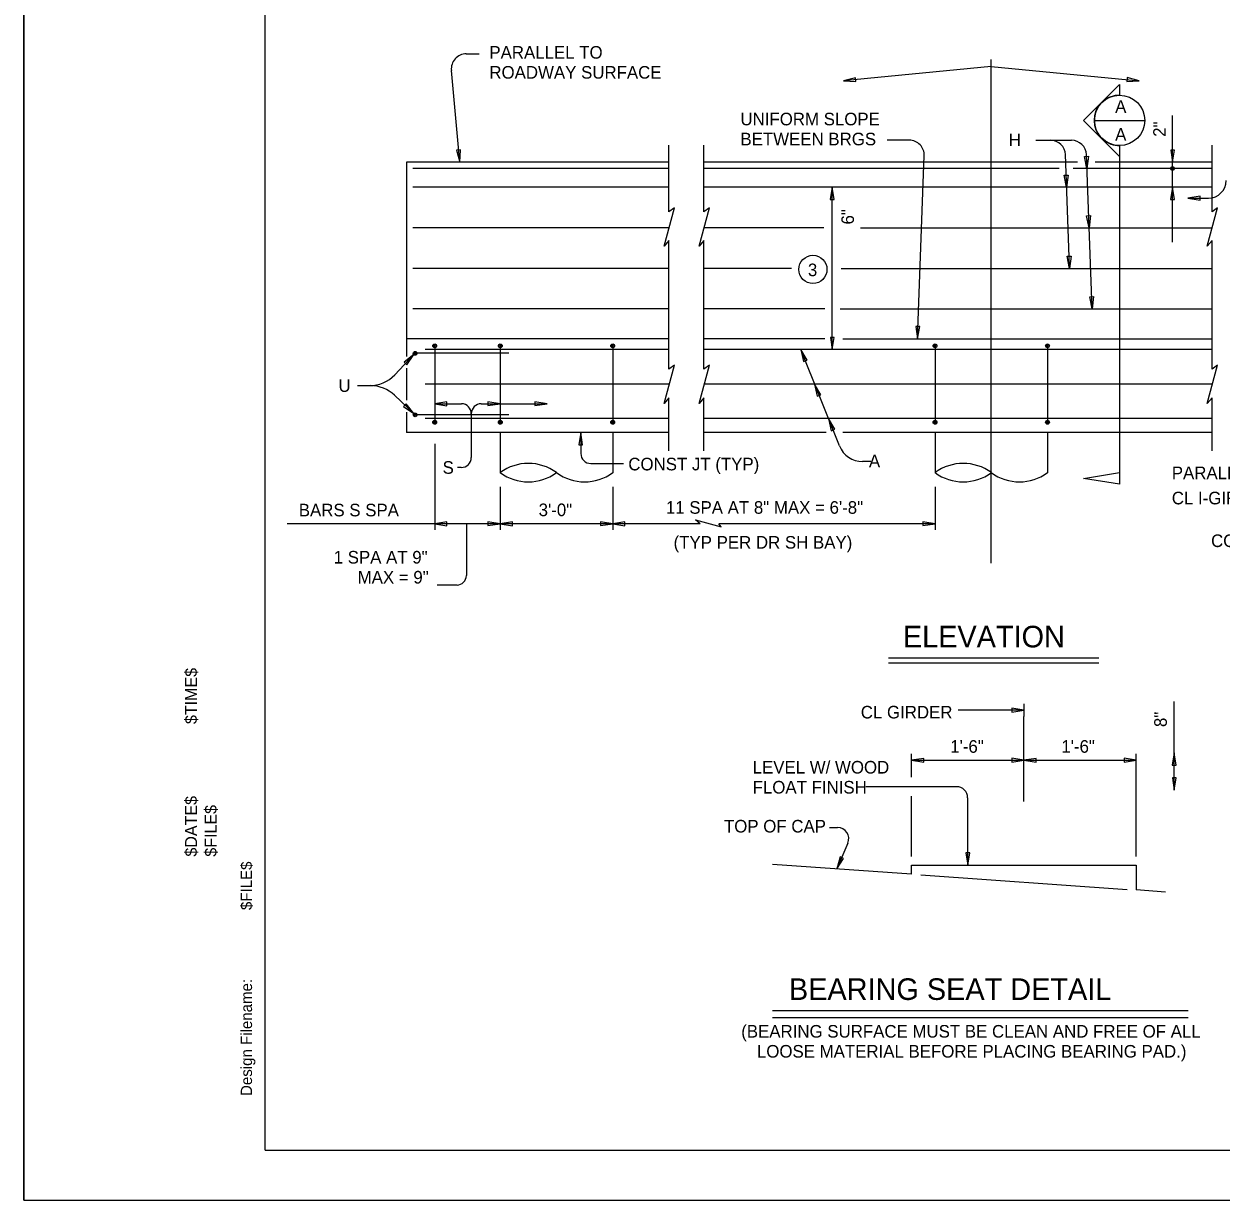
# Model space of a CAD drawing. Extents: x 970 to 1074, y 989 to 1045.
# Drawn here: x 1000 to 1011.98, y 997.81 to 1009.58 of the extents above; entities that cross this region are included whole.
import ezdxf

# ---------------------------------------------------------------- set-up
doc = ezdxf.new("R2010")
doc.units = 0
for name, color, linetype in [('BORD_lines_major', 7, 'Continuous'), ('BORD_text_filename_date', 7, 'Continuous'), ('D_BATCH_PLOT', 7, 'Continuous'), ('D_SHEET', 7, 'Continuous'), ('D_SHEET_TXT_SUB_CODE', 7, 'Continuous'), ('Default', 7, 'Continuous'), ('Working Level 1', 7, 'Continuous')]:
    doc.layers.add(name, color=color, linetype=linetype)

msp = doc.modelspace()

# ---------------------------------------------------------------- linework, layer by layer
at = {"layer": 'BORD_lines_major'}
for q in [(1002.413, 1019.195), (1033.5, 998.313)]:
    msp.add_line((1002.413, 998.313), q, dxfattribs=at)
at = {"layer": 'D_BATCH_PLOT'}
msp.add_lwpolyline([(1000, 997.813), (1034, 997.813), (1034, 1019.813), (1000, 1019.813)], close=True, dxfattribs=at)
at = {"layer": 'D_SHEET'}
for q in [(1000, 1019.813), (1034, 997.813)]:
    msp.add_line((1000, 997.813), q, dxfattribs=at)
at = {"layer": 'Default'}
msp.add_line((1010.71, 1008.614), (1011.214, 1008.614), dxfattribs=at)
for points in [[(1010.962, 1008.866), (1010.94, 1008.865), (1010.919, 1008.862), (1010.897, 1008.857), (1010.876, 1008.851), (1010.856, 1008.842), (1010.836, 1008.832), (1010.818, 1008.82), (1010.8, 1008.807), (1010.784, 1008.792), (1010.769, 1008.776), (1010.756, 1008.759), (1010.744, 1008.74), (1010.734, 1008.721), (1010.726, 1008.7), (1010.719, 1008.679), (1010.714, 1008.658), (1010.711, 1008.636), (1010.71, 1008.614), (1010.711, 1008.592), (1010.714, 1008.57), (1010.719, 1008.549), (1010.726, 1008.528), (1010.734, 1008.508), (1010.744, 1008.488), (1010.756, 1008.469), (1010.769, 1008.452), (1010.784, 1008.436), (1010.8, 1008.421), (1010.818, 1008.408), (1010.836, 1008.396), (1010.856, 1008.386), (1010.876, 1008.377), (1010.897, 1008.371), (1010.919, 1008.366), (1010.94, 1008.363), (1010.962, 1008.362), (1010.962, 1008.254), (1010.602, 1008.614), (1010.962, 1008.974)], [(1010.962, 1004.975), (1010.602, 1005.033), (1010.962, 1005.091)]]:
    msp.add_lwpolyline(points, close=True, dxfattribs=at)
msp.add_lwpolyline([(1010.962, 1008.362), (1010.962, 1004.975)], dxfattribs=at)
msp.add_circle((1010.962, 1008.614), 0.252, dxfattribs=at)
at = {"layer": 'Working Level 1'}
for p, q in [((1004.426, 1009.28), (1004.555, 1009.28)), ((1009.679, 1009.152), (1008.199, 1009.011)), ((1009.679, 1004.183), (1009.679, 1009.225)), ((1009.679, 1009.152), (1011.158, 1009.011)), ((1004.36, 1008.195), (1004.277, 1009.114)), ((1011.493, 1007.397), (1011.493, 1008.665)), ((1008.858, 1008.416), (1008.636, 1008.416)), ((1010.125, 1008.416), (1010.481, 1008.416)), ((1006.453, 1007.699), (1006.453, 1008.368)), ((1006.804, 1007.699), (1006.804, 1008.368)), ((1011.888, 1007.699), (1011.888, 1008.368)), ((1006.453, 1008.195), (1003.828, 1008.195)), ((1003.828, 1008.195), (1003.828, 1006.43)), ((1010.541, 1008.195), (1006.804, 1008.195)), ((1008.939, 1006.43), (1009.008, 1008.261)), ((1010.463, 1007.155), (1010.421, 1008.272)), ((1010.688, 1006.728), (1010.63, 1008.272)), ((1011.888, 1008.195), (1010.719, 1008.195)), ((1006.453, 1008.133), (1003.891, 1008.133)), ((1010.358, 1008.133), (1006.804, 1008.133)), ((1011.888, 1008.133), (1010.497, 1008.133)), ((1006.453, 1007.945), (1003.891, 1007.945)), ((1011.888, 1007.945), (1006.804, 1007.945)), ((1008.088, 1006.322), (1008.088, 1007.945)), ((1011.645, 1007.837), (1011.853, 1007.837)), ((1006.405, 1007.355), (1006.509, 1007.739)), ((1006.509, 1007.739), (1006.453, 1007.699)), ((1006.755, 1007.355), (1006.859, 1007.739)), ((1006.859, 1007.739), (1006.804, 1007.699)), ((1011.839, 1007.355), (1011.943, 1007.739)), ((1011.943, 1007.739), (1011.888, 1007.699)), ((1006.455, 1007.539), (1003.891, 1007.539)), ((1008.003, 1007.539), (1006.805, 1007.539)), ((1008.37, 1007.539), (1011.889, 1007.539)), ((1006.453, 1007.413), (1006.405, 1007.355)), ((1006.453, 1006.126), (1006.453, 1007.413)), ((1006.804, 1007.413), (1006.755, 1007.355)), ((1006.804, 1006.126), (1006.804, 1007.413)), ((1011.888, 1007.413), (1011.839, 1007.355)), ((1011.888, 1006.126), (1011.888, 1007.413)), ((1006.453, 1007.134), (1003.891, 1007.134)), ((1007.68, 1007.134), (1006.804, 1007.134)), ((1008.176, 1007.134), (1011.888, 1007.134)), ((1006.453, 1006.728), (1003.891, 1006.728)), ((1008.015, 1006.728), (1006.804, 1006.728)), ((1008.167, 1006.728), (1011.888, 1006.728)), ((1006.453, 1006.43), (1003.828, 1006.43)), ((1003.828, 1006.43), (1003.828, 1006.251)), ((1008.015, 1006.43), (1006.804, 1006.43)), ((1008.194, 1006.43), (1009.679, 1006.43)), ((1009.669, 1006.43), (1011.888, 1006.43)), ((1003.901, 1006.271), (1003.711, 1006.07)), ((1004.852, 1006.284), (1003.914, 1006.284)), ((1006.453, 1006.322), (1004.016, 1006.322)), ((1004.11, 1006.359), (1004.11, 1005.594)), ((1004.766, 1006.359), (1004.766, 1005.594)), ((1005.891, 1006.359), (1005.891, 1005.594)), ((1011.888, 1006.322), (1006.804, 1006.322)), ((1008.159, 1005.358), (1007.772, 1006.322)), ((1009.116, 1006.359), (1009.116, 1005.594)), ((1010.241, 1006.359), (1010.241, 1005.594)), ((1006.405, 1005.781), (1006.509, 1006.166)), ((1006.509, 1006.166), (1006.453, 1006.126)), ((1006.755, 1005.781), (1006.859, 1006.166)), ((1006.859, 1006.166), (1006.804, 1006.126)), ((1011.839, 1005.781), (1011.943, 1006.166)), ((1011.943, 1006.166), (1011.888, 1006.126)), ((1003.828, 1006.134), (1003.828, 1005.814)), ((1003.339, 1005.961), (1003.467, 1005.961)), ((1006.458, 1005.976), (1004.016, 1005.976)), ((1011.892, 1005.976), (1006.808, 1005.976)), ((1003.708, 1005.864), (1003.901, 1005.682)), ((1004.11, 1005.78), (1004.379, 1005.78)), ((1004.576, 1005.78), (1005.235, 1005.78)), ((1006.453, 1005.84), (1006.405, 1005.781)), ((1006.453, 1005.307), (1006.453, 1005.84)), ((1006.804, 1005.84), (1006.755, 1005.781)), ((1006.804, 1005.307), (1006.804, 1005.84)), ((1011.888, 1005.84), (1011.839, 1005.781)), ((1011.888, 1005.307), (1011.888, 1005.84)), ((1003.828, 1005.697), (1003.828, 1005.492)), ((1004.852, 1005.669), (1003.914, 1005.669)), ((1004.476, 1005.68), (1004.476, 1005.241)), ((1006.453, 1005.631), (1004.016, 1005.631)), ((1011.888, 1005.631), (1006.804, 1005.631)), ((1006.453, 1005.492), (1003.828, 1005.492)), ((1004.766, 1005.492), (1004.766, 1005.09)), ((1005.572, 1005.492), (1005.572, 1005.281)), ((1005.891, 1005.492), (1005.891, 1005.09)), ((1008.028, 1005.492), (1006.804, 1005.492)), ((1011.888, 1005.492), (1008.194, 1005.492)), ((1009.116, 1005.492), (1009.116, 1005.09)), ((1009.116, 1005.492), (1009.116, 1005.09)), ((1009.116, 1005.492), (1009.116, 1005.09)), ((1009.116, 1005.492), (1009.116, 1005.09)), ((1009.116, 1005.492), (1009.116, 1005.09)), ((1009.116, 1005.492), (1009.116, 1005.09)), ((1010.241, 1005.492), (1010.241, 1005.09)), ((1004.11, 1005.377), (1004.11, 1004.519)), ((1005.672, 1005.181), (1005.998, 1005.181)), ((1008.473, 1005.201), (1008.391, 1005.201)), ((1004.376, 1005.141), (1004.338, 1005.141)), ((1004.766, 1004.949), (1004.766, 1004.519)), ((1005.891, 1004.949), (1005.891, 1004.519)), ((1009.116, 1004.949), (1009.116, 1004.519)), ((1006.765, 1004.579), (1002.635, 1004.579)), ((1004.427, 1004.579), (1004.427, 1004.06)), ((1006.765, 1004.579), (1006.719, 1004.617)), ((1006.719, 1004.617), (1006.975, 1004.548)), ((1006.975, 1004.548), (1006.953, 1004.579)), ((1009.116, 1004.579), (1006.953, 1004.579)), ((1004.333, 1003.966), (1004.133, 1003.966)), ((1008.65, 1003.239), (1010.756, 1003.239)), ((1008.65, 1003.189), (1010.756, 1003.189)), ((1011.509, 1001.913), (1011.509, 1002.8)), ((1010.005, 1002.714), (1009.349, 1002.714)), ((1010.005, 1002.776), (1010.005, 1002.651)), ((1010.005, 1001.799), (1010.005, 1002.651)), ((1008.88, 1002.043), (1008.88, 1002.276)), ((1008.88, 1002.214), (1011.13, 1002.214)), ((1011.13, 1001.251), (1011.13, 1002.276)), ((1008.423, 1001.949), (1009.33, 1001.949)), ((1008.88, 1001.251), (1008.88, 1001.855)), ((1009.443, 1001.164), (1009.443, 1001.836)), ((1008.06, 1001.54), (1008.141, 1001.54)), ((1008.244, 1001.384), (1008.135, 1001.126)), ((1008.88, 1001.073), (1007.49, 1001.171)), ((1008.88, 1001.164), (1011.13, 1001.164)), ((1008.88, 1001.073), (1008.88, 1001.164)), ((1011.13, 1001.164), (1011.13, 1000.915)), ((1008.974, 1001.067), (1011.037, 1000.92)), ((1011.423, 1000.894), (1011.13, 1000.915)), ((1007.489, 999.708), (1011.649, 999.708)), ((1007.489, 999.638), (1011.649, 999.638))]:
    msp.add_line(p, q, dxfattribs=at)
for points in [[(1008.199, 1009.011), (1008.323, 1009.003), (1008.32, 1009.041)], [(1011.158, 1009.011), (1011.038, 1009.042), (1011.034, 1009.004)], [(1004.36, 1008.195), (1004.367, 1008.319), (1004.328, 1008.315)], [(1011.493, 1008.195), (1011.513, 1008.318), (1011.475, 1008.318)], [(1010.636, 1008.133), (1010.611, 1008.254), (1010.65, 1008.256)], [(1010.433, 1007.945), (1010.409, 1008.067), (1010.447, 1008.068)], [(1008.088, 1007.945), (1008.068, 1007.823), (1008.107, 1007.823)], [(1011.493, 1007.945), (1011.473, 1007.823), (1011.512, 1007.823)], [(1011.645, 1007.837), (1011.768, 1007.817), (1011.768, 1007.856)], [(1010.658, 1007.539), (1010.633, 1007.661), (1010.672, 1007.662)], [(1010.463, 1007.134), (1010.439, 1007.255), (1010.478, 1007.257)], [(1010.688, 1006.728), (1010.664, 1006.849), (1010.702, 1006.851)], [(1008.939, 1006.43), (1008.964, 1006.551), (1008.925, 1006.553)], [(1008.088, 1006.322), (1008.108, 1006.444), (1008.069, 1006.444)], [(1003.901, 1006.271), (1003.803, 1006.196), (1003.831, 1006.169)], [(1007.772, 1006.322), (1007.799, 1006.201), (1007.835, 1006.215)], [(1007.91, 1005.976), (1007.937, 1005.855), (1007.973, 1005.87)], [(1003.901, 1005.682), (1003.826, 1005.78), (1003.799, 1005.752)], [(1004.11, 1005.78), (1004.232, 1005.76), (1004.232, 1005.799)], [(1004.766, 1005.78), (1004.643, 1005.8), (1004.643, 1005.762)], [(1005.235, 1005.78), (1005.112, 1005.8), (1005.112, 1005.762)], [(1008.049, 1005.631), (1008.076, 1005.51), (1008.112, 1005.524)], [(1005.572, 1005.492), (1005.552, 1005.37), (1005.59, 1005.37)], [(1004.11, 1004.579), (1004.232, 1004.559), (1004.232, 1004.598)], [(1004.766, 1004.579), (1004.643, 1004.599), (1004.643, 1004.561)], [(1004.766, 1004.579), (1004.888, 1004.559), (1004.888, 1004.598)], [(1005.891, 1004.579), (1005.768, 1004.599), (1005.768, 1004.561)], [(1005.891, 1004.579), (1006.013, 1004.559), (1006.013, 1004.598)], [(1009.116, 1004.579), (1008.994, 1004.599), (1008.994, 1004.561)], [(1010.005, 1002.714), (1009.883, 1002.734), (1009.883, 1002.695)], [(1008.88, 1002.214), (1009.003, 1002.194), (1009.003, 1002.232)], [(1010.005, 1002.214), (1009.883, 1002.234), (1009.883, 1002.195)], [(1010.005, 1002.214), (1010.128, 1002.194), (1010.128, 1002.232)], [(1011.13, 1002.214), (1011.008, 1002.234), (1011.008, 1002.195)], [(1011.509, 1002.288), (1011.489, 1002.165), (1011.528, 1002.165)], [(1011.509, 1001.913), (1011.529, 1002.036), (1011.491, 1002.036)], [(1008.135, 1001.126), (1008.201, 1001.231), (1008.166, 1001.246)], [(1009.443, 1001.164), (1009.463, 1001.286), (1009.424, 1001.286)]]:
    msp.add_lwpolyline(points, close=True, dxfattribs=at)
for centre, radius in [((1011.493, 1008.133), 0.0187), ((1011.493, 1008.133), 0.0117), ((1011.493, 1008.133), 0.00469), ((1007.894, 1007.124), 0.141), ((1004.11, 1006.359), 0.0187), ((1004.766, 1006.359), 0.0187), ((1005.891, 1006.359), 0.0187), ((1009.116, 1006.359), 0.0187), ((1010.241, 1006.359), 0.0187), ((1003.914, 1006.284), 0.0187), ((1003.914, 1006.284), 0.0117), ((1003.914, 1006.284), 0.00469), ((1004.11, 1006.359), 0.0117), ((1004.11, 1006.359), 0.00469), ((1004.766, 1006.359), 0.0117), ((1004.766, 1006.359), 0.00469), ((1005.891, 1006.359), 0.0117), ((1005.891, 1006.359), 0.00469), ((1009.116, 1006.359), 0.0117), ((1009.116, 1006.359), 0.00469), ((1010.241, 1006.359), 0.0117), ((1010.241, 1006.359), 0.00469), ((1003.914, 1005.669), 0.0187), ((1003.914, 1005.669), 0.0117), ((1003.914, 1005.669), 0.00469), ((1004.11, 1005.594), 0.0187), ((1004.11, 1005.594), 0.0117), ((1004.11, 1005.594), 0.00469), ((1004.766, 1005.594), 0.0187), ((1004.766, 1005.594), 0.0117), ((1004.766, 1005.594), 0.00469), ((1005.891, 1005.594), 0.0187), ((1005.891, 1005.594), 0.0117), ((1005.891, 1005.594), 0.00469), ((1009.116, 1005.594), 0.0187), ((1009.116, 1005.594), 0.0117), ((1009.116, 1005.594), 0.00469), ((1010.241, 1005.594), 0.0187), ((1010.241, 1005.594), 0.0117), ((1010.241, 1005.594), 0.00469)]:
    msp.add_circle(centre, radius, dxfattribs=at)
for centre, radius, start, end in [((1004.426, 1009.13), 0.15, 90, 186.147), ((1008.858, 1008.266), 0.15, 357.861, 90), ((1010.271, 1008.266), 0.15, 2.1377, 90), ((1010.481, 1008.266), 0.15, 2.14, 90), ((1011.853, 1008.012), 0.175, 270, 0), ((1003.457, 1006.311), 0.35, 270, 316.4606), ((1003.467, 1005.611), 0.35, 46.4299, 90), ((1004.376, 1005.68), 0.1, 0, 88.1727), ((1004.576, 1005.68), 0.1, 90, 180), ((1008.391, 1005.451), 0.25, 201.8559, 270), ((1004.376, 1005.242), 0.1, 270, 360), ((1005.047, 1004.709), 0.474, 53.5974, 126.4026), ((1005.672, 1005.282), 0.1, 180, 270), ((1009.398, 1004.709), 0.474, 53.5974, 126.4026), ((1009.398, 1004.709), 0.474, 53.5974, 126.4026), ((1009.398, 1004.709), 0.474, 53.5974, 126.4026), ((1009.398, 1004.709), 0.474, 53.5974, 126.4026), ((1009.398, 1004.709), 0.474, 53.5974, 126.4026), ((1009.398, 1004.709), 0.474, 53.5974, 126.4026), ((1005.047, 1005.472), 0.474, 233.5974, 306.4026), ((1005.61, 1005.472), 0.474, 233.5974, 306.4026), ((1009.398, 1005.472), 0.474, 233.5974, 306.4026), ((1009.398, 1005.472), 0.474, 233.5974, 306.4026), ((1009.398, 1005.472), 0.474, 233.5974, 306.4026), ((1009.398, 1005.472), 0.474, 233.5974, 306.4026), ((1009.398, 1005.472), 0.474, 233.5974, 306.4026), ((1009.398, 1005.472), 0.474, 233.5974, 306.4026), ((1009.96, 1005.472), 0.474, 233.5974, 306.4026), ((1004.333, 1004.06), 0.0938, 270, 0), ((1009.33, 1001.836), 0.112, 0, 90), ((1008.141, 1001.428), 0.112, 337.1387, 90)]:
    msp.add_arc(centre, radius, start, end, dxfattribs=at)

# ---------------------------------------------------------------- texts
at = {"layer": 'BORD_text_filename_date'}
for s, height, p in [('$FILE$', 0.1126, (1002.282, 1000.714)), ('Design Filename:', 0.11256, (1002.282, 998.854))]:
    msp.add_text(s, height=height, rotation=89.9834, dxfattribs=at).set_placement(p)
at = {"layer": 'D_SHEET_TXT_SUB_CODE'}
for s, p in [('$TIME$', (1001.732, 1002.575)), ('$DATE$', (1001.732, 1001.249)), ('$FILE$', (1001.929, 1001.248))]:
    msp.add_text(s, height=0.12, rotation=90, dxfattribs=at).set_placement(p)
at = {"layer": 'Default'}
for p in [(1010.918, 1008.69), (1010.918, 1008.412)]:
    msp.add_text('A', height=0.126, dxfattribs=at).set_placement(p)
at = {"layer": 'Working Level 1'}
for s, height, p in [('PARALLEL TO', 0.126, (1004.657, 1009.232)), ('ROADWAY SURFACE', 0.126, (1004.657, 1009.032)), ('UNIFORM SLOPE', 0.126, (1007.169, 1008.565)), ('BETWEEN BRGS', 0.126, (1007.169, 1008.365)), (' H', 0.126, (1009.807, 1008.357)), ('3', 0.126, (1007.844, 1007.056)), ('U ', 0.126, (1003.147, 1005.898)), ('S ', 0.126, (1004.189, 1005.079)), ('CONST JT (TYP)', 0.126, (1006.047, 1005.113)), (' A ', 0.126, (1008.408, 1005.144)), ('PARALLEL TO', 0.126, (1011.485, 1005.025)), ('CL I-GIRDER', 0.126, (1011.485, 1004.773)), ('BARS S SPA', 0.126, (1002.75, 1004.653)), ('3\'-0"', 0.126, (1005.15, 1004.655)), ('11 SPA AT 8" MAX = 6\'-8"', 0.126, (1006.423, 1004.679)), ('(TYP PER DR SH BAY)', 0.126, (1006.5, 1004.33)), ('CONST JT (TYP)', 0.126, (1011.878, 1004.346)), ('1 SPA AT 9"', 0.126, (1003.099, 1004.181)), ('MAX = 9"', 0.126, (1003.339, 1003.981)), ('ELEVATION', 0.216, (1008.794, 1003.342)), ('CL GIRDER', 0.126, (1008.373, 1002.631)), ('1\'-6"', 0.126, (1009.268, 1002.288)), ('1\'-6"', 0.126, (1010.38, 1002.288)), ('LEVEL W/ WOOD', 0.126, (1007.291, 1002.08)), ('FLOAT FINISH', 0.126, (1007.291, 1001.88)), ('TOP OF CAP', 0.126, (1007.004, 1001.49)), ('BEARING SEAT DETAIL', 0.216, (1007.654, 999.815)), ('(BEARING SURFACE MUST BE CLEAN AND FREE OF ALL', 0.126, (1007.177, 999.438)), ('LOOSE MATERIAL BEFORE PLACING BEARING PAD.)', 0.126, (1007.334, 999.238))]:
    msp.add_text(s, height=height, dxfattribs=at).set_placement(p)
for s, p in [('2"', (1011.425, 1008.45)), ('6"', (1008.305, 1007.573)), ('8"', (1011.435, 1002.545))]:
    msp.add_text(s, height=0.126, rotation=90, dxfattribs=at).set_placement(p)

doc.saveas('drawing.dxf')
